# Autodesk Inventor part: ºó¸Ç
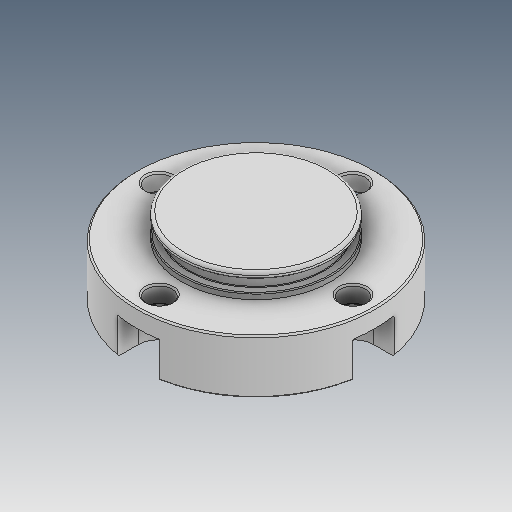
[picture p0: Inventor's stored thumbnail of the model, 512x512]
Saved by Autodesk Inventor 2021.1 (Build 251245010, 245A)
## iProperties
Created: 2013-04
Part Number: ºó¸Ç
Material: Ogólny
Document SubType Name: Modeling
Designer: user
Density: 1 g/cm^3
Appearance: Domyślna
Author: user
Revision Number: ÈÎºÎ
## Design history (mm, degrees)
feature "µ¹½Ç4"
node "Bryła1"
